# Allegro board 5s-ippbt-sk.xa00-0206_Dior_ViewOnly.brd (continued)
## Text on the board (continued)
User.45: list("[Package] BOTTOM" "196.Pkg to Place Keepin Spacing" "0 MIL [NONE]" "0 MIL" "0.00 MIL" "DRC ERROR CLASS/PACKAGE_BOTTOM" "[Shape] Package Keepin/All ((-353.71 -312.37) (4448.18 4461.96))" "[Shape] Package Geometry/Place_Bound_Bottom ((-360.18 172.48) (-131.49 627.92))" list(-353.710000 172.480000) nil)@@@list("amy_chou" "2015/01/12 09:59:30" nil "P143000034-PC" "5s-ippbt-sk.x01")@@@list("jennifer_hsu" "2015/01/12 14:37:48" nil "p143000039-pc" "5s-ippbt-sk.x01") | list("[Package] TOP" "146.Pkg to Place Keepin Spacing" "0 MIL [NONE]" "0 MIL" "0.00 MIL" "DRC ERROR CLASS/PACKAGE_TOP" "[Shape] Package Keepin/All ((-353.71 -312.37) (4448.18 4461.96))" "[Shape] Package Geometry/Place_Bound_Top ((-416.13 1530.26) (300.78 2667.86))" list(-314.340000 2622.640000) nil)@@@list("amy_chou" "2015/01/12 09:58:59" nil "P143000034-PC" "5s-ippbt-sk.x01")@@@list("jennifer_hsu" "2015/01/12 14:37:29" nil "p143000039-pc" "5s-ippbt-sk.x01") | list("[Package] TOP" "1.Pkg to Place Keepout Spacing" "0 MIL [NONE]" "122.05 MIL" "-122.05 MIL" "DRC ERROR CLASS/PACKAGE_TOP" "[Shape] Package Geometry/Place_Bound_Top ((-416.13 1530.26) (300.78 2667.86))" "[Shape] Package Keepout/Top ((-436.13 1510.26) (320.78 2687.86))" list(-287.050000 2630.860000) nil)@@@list("amy_chou" "2015/01/12 12:03:11" nil "P143000034-PC" "5s-ippbt-sk.x01")@@@nil | list("[Package] TOP" "145.Pkg to Place Keepout Spacing" "0 MIL [NONE]" "122.05 MIL" "-122.05 MIL" "DRC ERROR CLASS/PACKAGE_TOP" "[Shape] Package Keepout/Top ((-436.13 1510.26) (320.78 2687.86))" "[Shape] Package Geometry/Place_Bound_Top ((-416.13 1530.26) (300.78 2667.86))" list(-287.050000 1547.100000) nil)@@@list("amy_chou" "2015/01/12 09:58:59" nil "P143000034-PC" "5s-ippbt-sk.x01")@@@list("jennifer_hsu" "2015/01/12 14:37:28" nil "p143000039-pc" "5s-ippbt-sk.x01") | list("[Package] BOTTOM" "195.Pkg to Place Keepout Spacing" "0 MIL [NONE]" "198.82 MIL" "-198.82 MIL" "DRC ERROR CLASS/PACKAGE_BOTTOM" "[Shape] Package Keepout/Bottom ((-380.18 152.48) (-111.49 647.92))" "[Shape] Package Geometry/Place_Bound_Bottom ((-360.18 172.48) (-131.49 627.92))" list(-174.800000 627.920000) nil)@@@list("amy_chou" "2015/01/12 09:59:28" nil "P143000034-PC" "5s-ippbt-sk.x01")@@@list("jennifer_hsu" "2015/01/12 14:37:46" nil "p143000039-pc" "5s-ippbt-sk.x01") | list("[Package] BOTTOM" "4.Pkg to Place Keepout Spacing" "0 MIL [NONE]" "198.82 MIL" "-198.82 MIL" "DRC ERROR CLASS/PACKAGE_BOTTOM" "[Shape] Package Geometry/Place_Bound_Bottom ((-360.18 172.48) (-131.49 627.92))" "[Shape] Package Keepout/Bottom ((-380.18 152.48) (-111.49 647.92))" list(-174.800000 172.480000) nil)@@@list("amy_chou" "2015/01/09 17:09:16" nil "P143000034-PC" "5s-ippbt-sk.x01")@@@nil | list("[Package] BOTTOM" "181.Pkg to Place Keepout Spacing" "0 MIL [NONE]" "120 MIL" "-120.00 MIL" "DRC ERROR CLASS/PACKAGE_BOTTOM" "[Shape] Package Keepout/Bottom ((-380.18 152.48) (-111.49 647.92))" "[Shape] Package Geometry/Place_Bound_Bottom ((-237.19 -217.5) (197.81 217.5))" list(-154.910000 170.360000) nil)@@@list("amy_chou" "2015/01/12 09:59:19" nil "P143000034-PC" "5s-ippbt-sk.x01")@@@list("jennifer_hsu" "2015/01/12 14:37:41" nil "p143000039-pc" "5s-ippbt-sk.x01") | list("[Electrical] ALL" "127.Diffpair Max Uncoupled Length" "200 MIL [DIFFP_UNCOUPLED_LENGTH]" "226.3 MIL" "-26.30 MIL" "DRC ERROR CLASS/ALL" "[PinPair] <uTiL>cId2142<uTiL>.6:<uTiL>cId3537<uTiL>.AP10 ((-107.83 1959.21) (2741.31 1776.12))" "[PinPair] <uTiL>cId2142<uTiL>.5:<uTiL>cId3537<uTiL>.AP12 ((-107.83 1939.53) (2713.31 1776.12))" list(-107.830000 1939.530000) nil)@@@list("amy_chou" "2015/01/12 09:58:39" nil "P143000034-PC" "5s-ippbt-sk.x01")@@@list("jennifer_hsu" "2015/01/12 14:37:22" nil "p143000039-pc" "5s-ippbt-sk.x01") | list("[Package] TOP" "176.Pkg to Place Keepout Spacing" "0 MIL [NONE]" "78.74 MIL" "-78.74 MIL" "DRC ERROR CLASS/PACKAGE_TOP" "[Shape] Package Geometry/Place_Bound_Top ((-352.8 339.49) (-29.57 800.51))" "[Shape] Package Keepout/Top ((-372.8 319.49) (-9.57 820.51))" list(-29.570000 676.590000) nil)@@@list("amy_chou" "2015/01/12 09:59:16" nil "P143000034-PC" "5s-ippbt-sk.x01")@@@list("jennifer_hsu" "2015/01/12 14:37:39" nil "p143000039-pc" "5s-ippbt-sk.x01") | list("[Package] TOP" "171.Pkg to Pkg Spacing" "0 MIL [PACKAGE_HEIGHT_MIN]" "2 MIL" "-2.00 MIL" "DRC ERROR CLASS/PACKAGE_TOP" "[Shape] Package Geometry/Place_Bound_Top ((274.99 2677.45) (636.01 2871.55))" "[Shape] Package Geometry/Place_Bound_Top ((519.0 2748.19) (561.0 2791.81))" list(519.000000 2748.190000) nil)@@@list("amy_chou" "2015/01/12 09:59:14" nil "P143000034-PC" "5s-ippbt-sk.x01")@@@list("jennifer_hsu" "2015/01/12 14:37:38" nil "p143000039-pc" "5s-ippbt-sk.x01") | list("[Package] TOP" "162.Pkg to Place Keepout Spacing" "0 MIL [NONE]" "385.83 MIL" "-385.83 MIL" "DRC ERROR CLASS/PACKAGE_TOP" "[Shape] Package Geometry/Place_Bound_Top ((299.6 4003.36) (734.89 4575.0))" "[Shape] Package Keepout/Top ((219.6 3923.36) (814.89 4655.0))" list(535.930000 4007.140000) nil)@@@list("amy_chou" "2015/01/12 09:59:09" nil "P143000034-PC" "5s-ippbt-sk.x01")@@@list("jennifer_hsu" "2015/01/12 14:37:34" nil "p143000039-pc" "5s-ippbt-sk.x01") | list("[Package] TOP" "163.Pkg to Place Keepout Spacing" "0 MIL [PACKAGE_HEIGHT_MIN]" "385.83 MIL" "-385.83 MIL" "DRC ERROR CLASS/PACKAGE_TOP" "[Shape] Package Keepout/Top ((669.05 3600.32) (1555.75 4628.27))" "[Shape] Package Geometry/Place_Bound_Top ((299.6 4003.36) (734.89 4575.0))" list(669.050000 4015.550000) nil)@@@list("amy_chou" "2015/01/12 09:59:10" nil "P143000034-PC" "5s-ippbt-sk.x01")@@@list("jennifer_hsu" "2015/01/12 14:37:35" nil "p143000039-pc" "5s-ippbt-sk.x01") | list("[Package] TOP" "164.Pkg to Place Keepin Spacing" "0 MIL [NONE]" "0 MIL" "0.00 MIL" "DRC ERROR CLASS/PACKAGE_TOP" "[Shape] Package Keepin/All ((-353.71 -312.37) (4448.18 4461.96))" "[Shape] Package Geometry/Place_Bound_Top ((299.6 4003.36) (734.89 4575.0))" list(722.620000 4430.470000) nil)@@@list("amy_chou" "2015/01/12 09:59:10" nil "P143000034-PC" "5s-ippbt-sk.x01")@@@list("jennifer_hsu" "2015/01/12 14:37:35" nil "p143000039-pc" "5s-ippbt-sk.x01") | list("[Package] BOTTOM" "184.Pkg to Place Keepout Spacing" "0 MIL [NONE]" "393.7 MIL" "-393.70 MIL" "DRC ERROR CLASS/PACKAGE_BOTTOM" "[Shape] Package Keepout/Bottom ((728.52 749.93) (1290.38 3419.93))" "[Shape] Package Geometry/Place_Bound_Bottom ((145.87 510.78) (1222.38 3660.74))" list(728.520000 3335.560000) nil)@@@list("amy_chou" "2015/01/12 09:59:20" nil "P143000034-PC" "5s-ippbt-sk.x01")@@@list("jennifer_hsu" "2015/01/12 14:37:42" nil "p143000039-pc" "5s-ippbt-sk.x01") | list("[Package] TOP" "140.Pkg to Place Keepin Spacing" "0 MIL [NONE]" "0 MIL" "0.00 MIL" "DRC ERROR CLASS/PACKAGE_TOP" "[Shape] Package Keepin/All ((-353.71 -312.37) (4448.18 4461.96))" "[Shape] Package Geometry/Place_Bound_Top ((747.79 3679.06) (1477.01 4549.53))" list(790.350000 4430.470000) nil)@@@list("amy_chou" "2015/01/12 09:58:56" nil "P143000034-PC" "5s-ippbt-sk.x01")@@@list("jennifer_hsu" "2015/01/12 14:37:27" nil "p143000039-pc" "5s-ippbt-sk.x01") | list("[Package] TOP" "139.Pkg to Place Keepout Spacing" "0 MIL [NONE]" "656.69 MIL" "-656.69 MIL" "DRC ERROR CLASS/PACKAGE_TOP" "[Shape] Package Keepout/Top ((219.6 3923.36) (814.89 4655.0))" "[Shape] Package Geometry/Place_Bound_Top ((747.79 3679.06) (1477.01 4549.53))" list(802.620000 4549.530000) nil)@@@list("amy_chou" "2015/01/12 09:58:56" nil "P143000034-PC" "5s-ippbt-sk.x01")@@@list("jennifer_hsu" "2015/01/12 14:37:26" nil "p143000039-pc" "5s-ippbt-sk.x01") | list("[Package] TOP" "170.Pkg to Pkg Spacing" "0 MIL [PACKAGE_HEIGHT_MIN]" "248.03 MIL" "-248.03 MIL" "DRC ERROR CLASS/PACKAGE_TOP" "[Shape] Package Geometry/Place_Bound_Top ((800.94 1123.19) (856.56 1216.81))" "[Shape] Package Geometry/Place_Bound_Top ((686.82 1164.47) (970.68 1535.53))" list(856.560000 1164.470000) nil)@@@list("amy_chou" "2015/01/12 09:59:13" nil "P143000034-PC" "5s-ippbt-sk.x01")@@@list("jennifer_hsu" "2015/01/12 14:37:37" nil "p143000039-pc" "5s-ippbt-sk.x01") | list("[Package] BOTTOM" "190.Pkg to Pkg Spacing" "0 MIL [PACKAGE_HEIGHT_MIN]" "2 MIL" "-2.00 MIL" "DRC ERROR CLASS/PACKAGE_BOTTOM" "[Shape] Package Geometry/Place_Bound_Bottom ((913.39 482.9) (956.61 565.1))" "[Shape] Package Geometry/Place_Bound_Bottom ((863.19 462.19) (956.81 517.81))" list(913.390000 517.810000) nil)@@@list("amy_chou" "2015/01/12 09:59:24" nil "P143000034-PC" "5s-ippbt-sk.x01")@@@list("jennifer_hsu" "2015/01/12 14:37:44" nil "p143000039-pc" "5s-ippbt-sk.x01") | list("[Package] BOTTOM" "185.Pkg to Pkg Spacing" "0 MIL [PACKAGE_HEIGHT_MIN]" "248.03 MIL" "-248.03 MIL" "DRC ERROR CLASS/PACKAGE_BOTTOM" "[Shape] Package Geometry/Place_Bound_Bottom ((877.19 92.19) (970.81 147.81))" "[Shape] Package Geometry/Place_Bound_Bottom ((714.47 58.07) (1085.53 341.93))" list(924.000000 92.190000) nil)@@@list("amy_chou" "2015/01/12 09:59:21" nil "P143000034-PC" "5s-ippbt-sk.x01")@@@list("jennifer_hsu" "2015/01/12 14:37:42" nil "p143000039-pc" "5s-ippbt-sk.x01") | list("[Electrical] ALL" "135.Diffpair Max Uncoupled Length" "200 MIL [DIFFP_UNCOUPLED_LENGTH]" "258.41 MIL" "-58.41 MIL" "DRC ERROR CLASS/ALL" "[PinPair] <uTiL>cId3537<uTiL>.M52:<uTiL>cId1656<uTiL>.135 ((1924.04 2196.55) (1170.87 1654.66))" "[PinPair] <uTiL>cId3537<uTiL>.N53:<uTiL>cId1656<uTiL>.137 ((1908.88 2177.42) (1170.87 1631.04))" list(1170.870000 1631.040000) nil)@@@list("amy_chou" "2015/01/12 09:58:53" nil "P143000034-PC" "5s-ippbt-sk.x01")@@@list("jennifer_hsu" "2015/01/12 14:37:25" nil "p143000039-pc" "5s-ippbt-sk.x01") | list("[Package] BOTTOM" "189.Pkg to Pkg Spacing" "0 MIL [PACKAGE_HEIGHT_MIN]" "21.65 MIL" "-21.65 MIL" "DRC ERROR CLASS/PACKAGE_BOTTOM" "[Shape] Package Geometry/Place_Bound_Bottom ((1254.37 3476.81) (1325.63 3603.19))" "[Shape] Package Geometry/Place_Bound_Bottom ((1246.69 3478.98) (1333.31 3601.02))" list(1254.370000 3478.980000) nil)@@@list("amy_chou" "2015/01/12 09:59:23" nil "P143000034-PC" "5s-ippbt-sk.x01")@@@list("jennifer_hsu" "2015/01/12 14:37:44" nil "p143000039-pc" "5s-ippbt-sk.x01") | list("[Package] BOTTOM" "179.Pkg to Place Keepout Spacing" "0 MIL [NONE]" "70.87 MIL" "-70.87 MIL" "DRC ERROR CLASS/PACKAGE_BOTTOM" "[Shape] Package Keepout/Bottom ((728.52 749.93) (1290.38 3419.93))" "[Shape] Package Geometry/Place_Bound_Bottom ((1289.1 2201.54) (1569.12 2481.56))" list(1290.380000 2360.440000) nil)@@@list("amy_chou" "2015/01/12 09:59:18" nil "P143000034-PC" "5s-ippbt-sk.x01")@@@list("jennifer_hsu" "2015/01/12 14:37:40" nil "p143000039-pc" "5s-ippbt-sk.x01") | list("[Package] BOTTOM" "180.Pkg to Place Keepout Spacing" "0 MIL [NONE]" "70.87 MIL" "-70.87 MIL" "DRC ERROR CLASS/PACKAGE_BOTTOM" "[Shape] Package Keepout/Bottom ((728.52 749.93) (1290.38 3419.93))" "[Shape] Package Geometry/Place_Bound_Bottom ((1289.1 1414.14) (1569.12 1694.16))" list(1290.380000 1573.040000) nil)@@@list("amy_chou" "2015/01/12 09:59:18" nil "P143000034-PC" "5s-ippbt-sk.x01")@@@list("jennifer_hsu" "2015/01/12 14:37:41" nil "p143000039-pc" "5s-ippbt-sk.x01") | list("[Package] BOTTOM" "178.Pkg to Place Keepout Spacing" "0 MIL [NONE]" "220.47 MIL" "-220.47 MIL" "DRC ERROR CLASS/PACKAGE_BOTTOM" "[Shape] Package Keepout/Bottom ((728.52 749.93) (1290.38 3419.93))" "[Shape] Package Geometry/Place_Bound_Bottom ((1279.1 1044.99) (1579.12 1345.01))" list(1290.380000 1252.070000) nil)@@@list("amy_chou" "2015/01/12 09:59:17" nil "P143000034-PC" "5s-ippbt-sk.x01")@@@list("jennifer_hsu" "2015/01/12 14:37:40" nil "p143000039-pc" "5s-ippbt-sk.x01") | list("[Package] BOTTOM" "188.Pkg to Pkg Spacing" "0 MIL [PACKAGE_HEIGHT_MIN]" "21.65 MIL" "-21.65 MIL" "DRC ERROR CLASS/PACKAGE_BOTTOM" "[Shape] Package Geometry/Place_Bound_Bottom ((1344.37 3476.81) (1415.63 3603.19))" "[Shape] Package Geometry/Place_Bound_Bottom ((1336.69 3478.98) (1423.31 3601.02))" list(1344.370000 3478.980000) nil)@@@list("amy_chou" "2015/01/12 09:59:22" nil "P143000034-PC" "5s-ippbt-sk.x01")@@@list("jennifer_hsu" "2015/01/12 14:37:44" nil "p143000039-pc" "5s-ippbt-sk.x01") | list("[Package] TOP" "7.Pkg to Place Keepout Spacing" "0 MIL [PACKAGE_HEIGHT_MIN]" "656.69 MIL" "-656.69 MIL" "DRC ERROR CLASS/PACKAGE_TOP" "[Shape] Package Keepout/Top ((1418.61 3744.77) (2204.99 4634.92))" "[Shape] Package Geometry/Place_Bound_Top ((747.79 3679.06) (1477.01 4549.53))" list(1418.610000 4549.530000) nil)@@@list("amy_chou" "2015/01/12 18:28:01" nil "P143000034-PC" "5s-ippbt-sk.x01")@@@list("jennifer_hsu" "2015/01/12 18:35:55" nil "p143000039-pc" "5s-ippbt-sk.x01") | list("[Package] TOP" "137.Pkg to Place Keepout Spacing" "0 MIL [PACKAGE_HEIGHT_MIN]" "656.69 MIL" "-656.69 MIL" "DRC ERROR CLASS/PACKAGE_TOP" "[Shape] Package Keepout/Top ((669.05 3600.32) (1555.75 4628.27))" "[Shape] Package Geometry/Place_Bound_Top ((747.79 3679.06) (1477.01 4549.53))" list(1434.450000 4127.920000) nil)@@@list("amy_chou" "2015/01/12 09:58:55" nil "P143000034-PC" "5s-ippbt-sk.x01")@@@list("jennifer_hsu" "2015/01/12 14:37:26" nil "p143000039-pc" "5s-ippbt-sk.x01") | list("[Package] TOP" "138.Pkg to Place Keepout Spacing" "0 MIL [NONE]" "656.69 MIL" "-656.69 MIL" "DRC ERROR CLASS/PACKAGE_TOP" "[Shape] Package Keepout/Top ((1418.61 3750.77) (2204.99 4634.92))" "[Shape] Package Geometry/Place_Bound_Top ((747.79 3679.06) (1477.01 4549.53))" list(1434.450000 3782.980000) nil)@@@list("amy_chou" "2015/01/12 09:58:55" nil "P143000034-PC" "5s-ippbt-sk.x01")@@@list("jennifer_hsu" "2015/01/12 14:37:26" nil "p143000039-pc" "5s-ippbt-sk.x01") | list("[Package] BOTTOM" "186.Pkg to Pkg Spacing" "0 MIL [PACKAGE_HEIGHT_MIN]" "21.65 MIL" "-21.65 MIL" "DRC ERROR CLASS/PACKAGE_BOTTOM" "[Shape] Package Geometry/Place_Bound_Bottom ((1449.81 3667.37) (1576.19 3738.63))" "[Shape] Package Geometry/Place_Bound_Bottom ((1451.98 3659.69) (1574.02 3746.31))" list(1451.980000 3667.370000) nil)@@@list("amy_chou" "2015/01/12 09:59:21" nil "P143000034-PC" "5s-ippbt-sk.x01")@@@list("jennifer_hsu" "2015/01/12 14:37:43" nil "p143000039-pc" "5s-ippbt-sk.x01") | list("[Package] BOTTOM" "187.Pkg to Pkg Spacing" "0 MIL [PACKAGE_HEIGHT_MIN]" "21.65 MIL" "-21.65 MIL" "DRC ERROR CLASS/PACKAGE_BOTTOM" "[Shape] Package Geometry/Place_Bound_Bottom ((1451.81 3569.37) (1578.19 3640.63))" "[Shape] Package Geometry/Place_Bound_Bottom ((1453.98 3561.69) (1576.02 3648.31))" list(1453.980000 3569.370000) nil)@@@list("amy_chou" "2015/01/12 09:59:22" nil "P143000034-PC" "5s-ippbt-sk.x01")@@@list("jennifer_hsu" "2015/01/12 14:37:43" nil "p143000039-pc" "5s-ippbt-sk.x01") | list("[Package] TOP" "152.Pkg to Place Keepin Spacing" "0 MIL [NONE]" "0 MIL" "0.00 MIL" "DRC ERROR CLASS/PACKAGE_TOP" "[Shape] Package Keepin/All ((-353.71 -312.37) (4448.18 4461.96))" "[Shape] Package Geometry/Place_Bound_Top ((1498.61 3830.77) (2124.99 4554.92))" list(1498.610000 4430.470000) nil)@@@list("amy_chou" "2015/01/12 09:59:03" nil "P143000034-PC" "5s-ippbt-sk.x01")@@@list("jennifer_hsu" "2015/01/12 14:37:31" nil "p143000039-pc" "5s-ippbt-sk.x01") | list("[Package] TOP" "5.Pkg to Place Keepin Spacing" "0 MIL [NONE]" "0 MIL" "0.00 MIL" "DRC ERROR CLASS/PACKAGE_TOP" "[Shape] Package Keepin/All ((-353.71 -312.37) (4448.18 4461.96))" "[Shape] Package Geometry/Place_Bound_Top ((1498.61 3824.77) (2124.99 4554.92))" list(1498.610000 4430.470000) nil)@@@list("amy_chou" "2015/01/12 17:57:22" nil "P143000034-PC" "5s-ippbt-sk.x01")@@@list("jennifer_hsu" "2015/01/12 18:35:54" nil "p143000039-pc" "5s-ippbt-sk.x01") | list("[Package] TOP" "3.Pkg to Place Keepout Spacing" "0 MIL [PACKAGE_HEIGHT_MIN]" "639.76 MIL" "-639.76 MIL" "DRC ERROR CLASS/PACKAGE_TOP" "[Shape] Package Keepout/Top ((1418.61 3744.77) (2204.99 4634.92))" "[Shape] Package Geometry/Place_Bound_Top ((1498.61 3824.77) (2124.99 4554.92))" list(1498.610000 3824.770000) nil)@@@list("amy_chou" "2015/01/12 18:28:06" nil "P143000034-PC" "5s-ippbt-sk.x01")@@@list("jennifer_hsu" "2015/01/12 18:35:53" nil "p143000039-pc" "5s-ippbt-sk.x01") | list("[Package] TOP" "150.Pkg to Place Keepout Spacing" "0 MIL [PACKAGE_HEIGHT_MIN]" "639.76 MIL" "-639.76 MIL" "DRC ERROR CLASS/PACKAGE_TOP" "[Shape] Package Keepout/Top ((669.05 3600.32) (1555.75 4628.27))" "[Shape] Package Geometry/Place_Bound_Top ((1498.61 3830.77) (2124.99 4554.92))" list(1513.190000 4127.920000) nil)@@@list("amy_chou" "2015/01/12 09:59:02" nil "P143000034-PC" "5s-ippbt-sk.x01")@@@list("jennifer_hsu" "2015/01/12 14:37:30" nil "p143000039-pc" "5s-ippbt-sk.x01") | list("[Package] TOP" "4.Pkg to Place Keepout Spacing" "0 MIL [PACKAGE_HEIGHT_MIN]" "639.76 MIL" "-639.76 MIL" "DRC ERROR CLASS/PACKAGE_TOP" "[Shape] Package Keepout/Top ((669.05 3600.32) (1555.75 4628.27))" "[Shape] Package Geometry/Place_Bound_Top ((1498.61 3824.77) (2124.99 4554.92))" list(1513.190000 4127.920000) nil)@@@list("amy_chou" "2015/01/12 18:27:59" nil "P143000034-PC" "5s-ippbt-sk.x01")@@@list("jennifer_hsu" "2015/01/12 18:35:53" nil "p143000039-pc" "5s-ippbt-sk.x01") | list("[Package] TOP" "3.Pkg to Place Keepout Spacing" "0 MIL [PACKAGE_HEIGHT_MIN]" "639.76 MIL" "-639.76 MIL" "DRC ERROR CLASS/PACKAGE_TOP" "[Shape] Package Keepout/Top ((669.05 3600.32) (1555.75 4628.27))" "[Shape] Package Geometry/Place_Bound_Top ((1498.61 3824.77) (2124.99 4554.92))" list(1513.190000 3824.770000) nil)@@@list("amy_chou" "2015/01/12 17:57:28" nil "P143000034-PC" "5s-ippbt-sk.x01")@@@nil | list("[Package] TOP" "158.Pkg to Place Keepout Spacing" "0 MIL [NONE]" "165.35 MIL" "-165.35 MIL" "DRC ERROR CLASS/PACKAGE_TOP" "[Shape] Package Geometry/Place_Bound_Top ((1348.69 -332.07) (1730.95 554.15))" "[Shape] Package Keepout/Top ((1328.69 -352.07) (1750.95 574.15))" list(1730.950000 111.040000) nil)@@@list("amy_chou" "2015/01/12 09:59:07" nil "P143000034-PC" "5s-ippbt-sk.x01")@@@list("jennifer_hsu" "2015/01/12 14:37:33" nil "p143000039-pc" "5s-ippbt-sk.x01") | list("[Package] TOP" "159.Pkg to Place Keepin Spacing" "0 MIL [NONE]" "0 MIL" "0.00 MIL" "DRC ERROR CLASS/PACKAGE_TOP" "[Shape] Package Keepin/All ((-353.71 -312.37) (4448.18 4461.96))" "[Shape] Package Geometry/Place_Bound_Top ((1348.69 -332.07) (1730.95 554.15))" list(1730.950000 -266.490000) nil)@@@list("amy_chou" "2015/01/12 09:59:07" nil "P143000034-PC" "5s-ippbt-sk.x01")@@@list("jennifer_hsu" "2015/01/12 14:37:33" nil "p143000039-pc" "5s-ippbt-sk.x01") | list("[Package] TOP" "151.Pkg to Place Keepout Spacing" "0 MIL [NONE]" "639.76 MIL" "-639.76 MIL" "DRC ERROR CLASS/PACKAGE_TOP" "[Shape] Package Keepout/Top ((1418.61 3750.77) (2204.99 4634.92))" "[Shape] Package Geometry/Place_Bound_Top ((1498.61 3830.77) (2124.99 4554.92))" list(1811.800000 3830.770000) nil)@@@list("amy_chou" "2015/01/12 09:59:03" nil "P143000034-PC" "5s-ippbt-sk.x01")@@@list("jennifer_hsu" "2015/01/12 14:37:31" nil "p143000039-pc" "5s-ippbt-sk.x01") | list("[Package] TOP" "172.Pkg to Pkg Spacing" "0 MIL [PACKAGE_HEIGHT_MIN]" "47.24 MIL" "-47.24 MIL" "DRC ERROR CLASS/PACKAGE_TOP" "[Shape] Package Geometry/Place_Bound_Top ((1822.19 933.19) (1877.81 1026.81))" "[Shape] Package Geometry/Place_Bound_Top ((1600.35 958.49) (1904.12 1201.5))" list(1822.190000 1026.810000) nil)@@@list("amy_chou" "2015/01/12 09:59:14" nil "P143000034-PC" "5s-ippbt-sk.x01")@@@list("jennifer_hsu" "2015/01/12 14:37:38" nil "p143000039-pc" "5s-ippbt-sk.x01") | list("[Package] BOTTOM" "183.Pkg to Place Keepout Spacing" "0 MIL [NONE]" "43.31 MIL" "-43.31 MIL" "DRC ERROR CLASS/PACKAGE_BOTTOM" "[Shape] Package Geometry/Place_Bound_Bottom ((1828.98 -6.97) (1998.66 646.97))" "[Shape] Package Keepout/Bottom ((1808.98 -26.97) (2018.66 666.97))" list(1828.980000 320.000000) nil)@@@list("amy_chou" "2015/01/12 09:59:20" nil "P143000034-PC" "5s-ippbt-sk.x01")@@@list("jennifer_hsu" "2015/01/12 14:37:42" nil "p143000039-pc" "5s-ippbt-sk.x01") | list("[Electrical] ALL" "133.Relative Propagation Delay" "R_M_A_D7:G:::0.00 MIL:19.00 MIL [RELATIVE_PROPAGATION_DELAY]" "30.58 MIL" "" "DRC ERROR CLASS/ALL" "[PinPair] <uTiL>cId3537<uTiL>.AA51:<uTiL>cId1656<uTiL>.186 ((1938.15 2024.38) (848.03 1052.3))" "[PinPair] <uTiL>cId3537<uTiL>.AC53:<uTiL>cId1656<uTiL>.192 ((1908.88 1986.12) (848.03 981.43))" list(1908.880000 1986.120000) nil)@@@list("amy_chou" "2015/01/12 09:58:45" nil "P143000034-PC" "5s-ippbt-sk.x01")@@@list("jennifer_hsu" "2015/01/12 14:37:24" nil "p143000039-pc" "5s-ippbt-sk.x01") | list("[Electrical] ALL" "136.Diffpair Max Uncoupled Length" "200 MIL [DIFFP_UNCOUPLED_LENGTH]" "260.19 MIL" "-60.19 MIL" "DRC ERROR CLASS/ALL" "[PinPair] <uTiL>cId3537<uTiL>.N53:<uTiL>cId1656<uTiL>.137 ((1908.88 2177.42) (1170.87 1631.04))" "[PinPair] <uTiL>cId3537<uTiL>.M52:<uTiL>cId1656<uTiL>.135 ((1924.04 2196.55) (1170.87 1654.66))" list(1924.040000 2196.550000) nil)@@@list("amy_chou" "2015/01/12 09:58:54" nil "P143000034-PC" "5s-ippbt-sk.x01")@@@list("jennifer_hsu" "2015/01/12 14:37:25" nil "p143000039-pc" "5s-ippbt-sk.x01") | list("[Electrical] ALL" "134.Relative Propagation Delay" "R_M_A_D1:G:::0.00 MIL:19.00 MIL [RELATIVE_PROPAGATION_DELAY]" "39.19 MIL" "" "DRC ERROR CLASS/ALL" "[PinPair] <uTiL>cId3537<uTiL>.B34:<uTiL>cId1656<uTiL>.27 ((2279.46 2397.82) (1170.87 3024.74))" "[PinPair] <uTiL>cId3537<uTiL>.A37:<uTiL>cId1656<uTiL>.34 ((2222.07 2412.98) (848.03 2942.06))" list(2222.070000 2412.980000) nil)@@@list("amy_chou" "2015/01/12 09:58:52" nil "P143000034-PC" "5s-ippbt-sk.x01")@@@list("jennifer_hsu" "2015/01/12 14:37:25" nil "p143000039-pc" "5s-ippbt-sk.x01") | list("[Package] TOP" "155.Pkg to Place Keepin Spacing" "0 MIL [NONE]" "0 MIL" "0.00 MIL" "DRC ERROR CLASS/PACKAGE_TOP" "[Shape] Package Keepin/All ((-353.71 -312.37) (4448.18 4461.96))" "[Shape] Package Geometry/Place_Bound_Top ((2323.9 3629.31) (2669.82 4573.62))" list(2323.900000 4376.560000) nil)@@@list("amy_chou" "2015/01/12 09:59:05" nil "P143000034-PC" "5s-ippbt-sk.x01")@@@list("jennifer_hsu" "2015/01/12 14:37:32" nil "p143000039-pc" "5s-ippbt-sk.x01") | list("[Package] BOTTOM" "177.Pkg to Pkg Spacing" "0 MIL [PACKAGE_HEIGHT_MIN]" "57.09 MIL" "-57.09 MIL" "DRC ERROR CLASS/PACKAGE_BOTTOM" "[Shape] Package Geometry/Place_Bound_Bottom ((2347.19 758.19) (2402.81 851.81))" "[Shape] Package Geometry/Place_Bound_Bottom ((2284.91 733.54) (2395.09 796.46))" list(2347.190000 758.190000) nil)@@@list("amy_chou" "2015/01/12 09:59:17" nil "P143000034-PC" "5s-ippbt-sk.x01")@@@list("jennifer_hsu" "2015/01/12 14:37:40" nil "p143000039-pc" "5s-ippbt-sk.x01") | list("[Package] TOP" "153.Pkg to Place Keepout Spacing" "0 MIL [NONE]" "354.33 MIL" "-354.33 MIL" "DRC ERROR CLASS/PACKAGE_TOP" "[Shape] Package Keepout/Top ((2297.99 -322.01) (2642.01 -177.99))" "[Shape] Package Geometry/Place_Bound_Top ((2307.99 -312.01) (2632.01 -187.99))" list(2470.000000 -187.990000) nil)@@@list("amy_chou" "2015/01/12 09:59:04" nil "P143000034-PC" "5s-ippbt-sk.x01")@@@list("jennifer_hsu" "2015/01/12 14:37:31" nil "p143000039-pc" "5s-ippbt-sk.x01") | list("[Electrical] ALL" "114.Diffpair Max Uncoupled Length" "200 MIL [DIFFP_UNCOUPLED_LENGTH]" "221.63 MIL" "-21.63 MIL" "DRC ERROR CLASS/ALL" "[PinPair] <uTiL>cId4704<uTiL>.3:<uTiL>cId3537<uTiL>.AG1 ((2477.17 4106.69) (2917.86 1909.6))" "[PinPair] <uTiL>cId4704<uTiL>.1:<uTiL>cId3537<uTiL>.AG3 ((2477.17 4152.16) (2888.59 1909.6))" list(2477.170000 4152.160000) nil)@@@list("amy_chou" "2015/01/12 09:58:30" nil "P143000034-PC" "5s-ippbt-sk.x01")@@@list("jennifer_hsu" "2015/01/12 14:37:17" nil "p143000039-pc" "5s-ippbt-sk.x01") | list("[Electrical] ALL" "116.Diffpair Max Uncoupled Length" "200 MIL [DIFFP_UNCOUPLED_LENGTH]" "212.82 MIL" "-12.82 MIL" "DRC ERROR CLASS/ALL" "[PinPair] <uTiL>cId4704<uTiL>.9:<uTiL>cId3537<uTiL>.AD2 ((2477.17 3970.27) (2902.7 1966.99))" "[PinPair] <uTiL>cId4704<uTiL>.7:<uTiL>cId3537<uTiL>.AD3 ((2477.17 4015.75) (2874.6 1966.75))" list(2477.170000 4015.750000) nil)@@@list("amy_chou" "2015/01/12 09:58:31" nil "P143000034-PC" "5s-ippbt-sk.x01")@@@list("jennifer_hsu" "2015/01/12 14:37:18" nil "p143000039-pc" "5s-ippbt-sk.x01") | list("[Package] TOP" "173.Pkg to Pkg Spacing" "0 MIL [PACKAGE_HEIGHT_MIN]" "2 MIL" "-2.00 MIL" "DRC ERROR CLASS/PACKAGE_TOP" "[Shape] Package Geometry/Place_Bound_Top ((2488.19 2807.19) (2581.81 2862.81))" "[Shape] Package Geometry/Place_Bound_Top ((2488.19 2857.19) (2581.81 2912.81))" list(2488.190000 2862.810000) nil)@@@list("amy_chou" "2015/01/12 09:59:15" nil "P143000034-PC" "5s-ippbt-sk.x01")@@@list("jennifer_hsu" "2015/01/12 14:37:38" nil "p143000039-pc" "5s-ippbt-sk.x01") | list("[Electrical] ALL" "117.Diffpair Max Uncoupled Length" "200 MIL [DIFFP_UNCOUPLED_LENGTH]" "225.09 MIL" "-25.09 MIL" "DRC ERROR CLASS/ALL" "[PinPair] <uTiL>cId3537<uTiL>.AF2:<uTiL>cId4704<uTiL>.6 ((2902.7 1928.73) (2516.54 4038.46))" "[PinPair] <uTiL>cId4704<uTiL>.4:<uTiL>cId3537<uTiL>.AF3 ((2516.54 4083.94) (2874.6 1928.97))" list(2516.540000 4083.940000) nil)@@@list("amy_chou" "2015/01/12 09:58:32" nil "P143000034-PC" "5s-ippbt-sk.x01")@@@list("jennifer_hsu" "2015/01/12 14:37:18" nil "p143000039-pc" "5s-ippbt-sk.x01") | list("[Electrical] ALL" "130.Diffpair Max Uncoupled Length" "200 MIL [DIFFP_UNCOUPLED_LENGTH]" "223.62 MIL" "-23.62 MIL" "DRC ERROR CLASS/ALL" "[PinPair] <uTiL>cId3537<uTiL>.K16:<uTiL>cId3653<uTiL>.2 ((2623.43 2236.43) (4025.91 1634.72))" "[PinPair] <uTiL>cId3537<uTiL>.M16:<uTiL>cId3653<uTiL>.3 ((2623.43 2208.43) (4025.91 1713.46))" list(2623.430000 2208.430000) nil)@@@list("amy_chou" "2015/01/12 09:58:42" nil "P143000034-PC" "5s-ippbt-sk.x01")@@@list("jennifer_hsu" "2015/01/12 14:37:23" nil "p143000039-pc" "5s-ippbt-sk.x01") | list("[Electrical] ALL" "132.Diffpair Max Uncoupled Length" "200 MIL [DIFFP_UNCOUPLED_LENGTH]" "207.92 MIL" "-7.92 MIL" "DRC ERROR CLASS/ALL" "[PinPair] <uTiL>cId3537<uTiL>.G14:<uTiL>cId4801<uTiL>.2 ((2662.43 2292.43) (4054.67 2459.84))" "[PinPair] <uTiL>cId3537<uTiL>.J14:<uTiL>cId4801<uTiL>.3 ((2662.43 2264.43) (4054.67 2538.58))" list(2662.430000 2264.430000) nil)@@@list("amy_chou" "2015/01/12 09:58:44" nil "P143000034-PC" "5s-ippbt-sk.x01")@@@list("jennifer_hsu" "2015/01/12 14:37:24" nil "p143000039-pc" "5s-ippbt-sk.x01") | list("[Package] TOP" "154.Pkg to Place Keepout Spacing" "0 MIL [NONE]" "655.51 MIL" "-655.51 MIL" "DRC ERROR CLASS/PACKAGE_TOP" "[Shape] Package Geometry/Place_Bound_Top ((2323.9 3629.31) (2669.82 4573.62))" "[Shape] Package Keepout/Top ((2243.9 3549.31) (2749.82 4653.62))" list(2669.820000 4573.620000) nil)@@@list("amy_chou" "2015/01/12 09:59:04" nil "P143000034-PC" "5s-ippbt-sk.x01")@@@list("jennifer_hsu" "2015/01/12 14:37:32" nil "p143000039-pc" "5s-ippbt-sk.x01") | list("[Package] TOP" "165.Pkg to Place Keepout Spacing" "0 MIL [NONE]" "259.84 MIL" "-259.84 MIL" "DRC ERROR CLASS/PACKAGE_TOP" "[Shape] Package Geometry/Place_Bound_Top ((2769.44 -179.29) (2970.56 309.29))" "[Shape] Package Keepout/Top ((2749.44 -199.29) (2990.56 329.29))" list(2769.440000 309.290000) nil)@@@list("amy_chou" "2015/01/12 09:59:11" nil "P143000034-PC" "5s-ippbt-sk.x01")@@@list("jennifer_hsu" "2015/01/12 14:37:35" nil "p143000039-pc" "5s-ippbt-sk.x01") | list("[Electrical] ALL" "124.Diffpair Max Uncoupled Length" "200 MIL [DIFFP_UNCOUPLED_LENGTH]" "216.83 MIL" "-16.83 MIL" "DRC ERROR CLASS/ALL" "[PinPair] <uTiL>cId3537<uTiL>.BF6:<uTiL>cId555<uTiL>.2 ((2811.51 1544.77) (-63.23 638.9))" "[PinPair] <uTiL>cId555<uTiL>.3:<uTiL>cId3537<uTiL>.BG7 ((-63.23 619.21) (2789.48 1526.24))" list(2789.480000 1526.240000) nil)@@@list("amy_chou" "2015/01/12 09:58:36" nil "P143000034-PC" "5s-ippbt-sk.x01")@@@list("jennifer_hsu" "2015/01/12 14:37:21" nil "p143000039-pc" "5s-ippbt-sk.x01") | list("[Electrical] ALL" "128.Diffpair Max Uncoupled Length" "200 MIL [DIFFP_UNCOUPLED_LENGTH]" "203.01 MIL" "-3.01 MIL" "DRC ERROR CLASS/ALL" "[PinPair] <uTiL>cId3537<uTiL>.AP4:<uTiL>cId3651<uTiL>.14 ((2851.82 1775.09) (1713.62 3532.83))" "[PinPair] <uTiL>cId3537<uTiL>.AP6:<uTiL>cId3651<uTiL>.13 ((2825.31 1776.12) (1697.87 3532.83))" list(2825.310000 1776.120000) nil)@@@list("amy_chou" "2015/01/12 09:58:40" nil "P143000034-PC" "5s-ippbt-sk.x01")@@@list("jennifer_hsu" "2015/01/12 14:37:22" nil "p143000039-pc" "5s-ippbt-sk.x01") | list("[Electrical] ALL" "126.Diffpair Max Uncoupled Length" "200 MIL [DIFFP_UNCOUPLED_LENGTH]" "211.55 MIL" "-11.55 MIL" "DRC ERROR CLASS/ALL" "[PinPair] <uTiL>cId3537<uTiL>.AV4:<uTiL>cId1927<uTiL>.37 ((2851.82 1698.8) (1688.44 120.88))" "[PinPair] <uTiL>cId3537<uTiL>.AV6:<uTiL>cId1927<uTiL>.35 ((2825.31 1698.8) (1688.44 140.57))" list(2825.310000 1698.800000) nil)@@@list("amy_chou" "2015/01/12 09:58:38" nil "P143000034-PC" "5s-ippbt-sk.x01")@@@list("jennifer_hsu" "2015/01/12 14:37:21" nil "p143000039-pc" "5s-ippbt-sk.x01") | list("[Package] TOP" "157.Pkg to Place Keepin Spacing" "0 MIL [NONE]" "0 MIL" "0.00 MIL" "DRC ERROR CLASS/PACKAGE_TOP" "[Shape] Package Keepin/All ((-353.71 -312.37) (4448.18 4461.96))" "[Shape] Package Geometry/Place_Bound_Top ((2895.24 3525.39) (3222.4 4573.03))" list(2895.240000 4430.470000) nil)@@@list("amy_chou" "2015/01/12 09:59:06" nil "P143000034-PC" "5s-ippbt-sk.x01")@@@list("jennifer_hsu" "2015/01/12 14:37:33" nil "p143000039-pc" "5s-ippbt-sk.x01") | list("[Package] TOP" "6.Pkg to Place Keepout Spacing" "0 MIL [PACKAGE_HEIGHT_MIN]" "710.63 MIL" "-710.63 MIL" "DRC ERROR CLASS/PACKAGE_TOP" "[Shape] Package Keepout/Top ((2815.24 3445.39) (3302.4 4653.03))" "[Shape] Package Geometry/Place_Bound_Top ((2895.24 3525.39) (3222.4 4573.03))" list(2895.240000 3525.390000) nil)@@@list("amy_chou" "2015/01/12 18:28:00" nil "P143000034-PC" "5s-ippbt-sk.x01")@@@list("jennifer_hsu" "2015/01/12 18:35:54" nil "p143000039-pc" "5s-ippbt-sk.x01") | list("[Electrical] ALL" "115.Diffpair Max Uncoupled Length" "200 MIL [DIFFP_UNCOUPLED_LENGTH]" "253.06 MIL" "-53.06 MIL" "DRC ERROR CLASS/ALL" "[PinPair] <uTiL>cId4704<uTiL>.10:<uTiL>cId3537<uTiL>.AC3 ((2516.54 3947.52) (2888.59 1986.12))" "[PinPair] <uTiL>cId3537<uTiL>.AC1:<uTiL>cId4704<uTiL>.12 ((2917.86 1986.12) (2516.54 3902.05))" list(2917.860000 1986.120000) nil)@@@list("amy_chou" "2015/01/12 09:58:31" nil "P143000034-PC" "5s-ippbt-sk.x01")@@@list("jennifer_hsu" "2015/01/12 14:37:17" nil "p143000039-pc" "5s-ippbt-sk.x01") | list("[Electrical] ALL" "118.Diffpair Max Uncoupled Length" "200 MIL [DIFFP_UNCOUPLED_LENGTH]" "357.3 MIL" "-157.30 MIL" "DRC ERROR CLASS/ALL" "[PinPair] <uTiL>cId4621<uTiL>.1:<uTiL>cId3537<uTiL>.AL3 ((3042.4 3395.59) (2888.59 1833.08))" "[PinPair] <uTiL>cId3537<uTiL>.AL1:<uTiL>cId4621<uTiL>.4 ((2917.86 1833.08) (2967.6 3344.41))" list(2917.860000 1833.080000) nil)@@@list("amy_chou" "2015/01/12 09:58:33" nil "P143000034-PC" "5s-ippbt-sk.x01")@@@list("jennifer_hsu" "2015/01/12 14:37:18" nil "p143000039-pc" "5s-ippbt-sk.x01") | list("[Electrical] ALL" "121.Diffpair Max Uncoupled Length" "200 MIL [DIFFP_UNCOUPLED_LENGTH]" "302.68 MIL" "-102.68 MIL" "DRC ERROR CLASS/ALL" "[PinPair] <uTiL>cId3537<uTiL>.AR3:<uTiL>cId4703<uTiL>.7 ((2888.59 1756.56) (3029.29 3929.92))" "[PinPair] <uTiL>cId3537<uTiL>.AR1:<uTiL>cId4703<uTiL>.9 ((2917.86 1756.56) (3029.29 3878.74))" list(2917.860000 1756.560000) nil)@@@list("amy_chou" "2015/01/12 09:58:35" nil "P143000034-PC" "5s-ippbt-sk.x01")@@@list("jennifer_hsu" "2015/01/12 14:37:19" nil "p143000039-pc" "5s-ippbt-sk.x01") | list("[Package] TOP" "147.Pkg to Place Keepout Spacing" "0 MIL [NONE]" "259.84 MIL" "-259.84 MIL" "DRC ERROR CLASS/PACKAGE_TOP" "[Shape] Package Geometry/Place_Bound_Top ((2769.44 -179.29) (2970.56 309.29))" "[Shape] Package Keepout/Top ((2919.55 -318.35) (3300.93 119.6))" list(2970.560000 -90.030000) nil)@@@list("amy_chou" "2015/01/12 09:59:00" nil "P143000034-PC" "5s-ippbt-sk.x01")@@@list("jennifer_hsu" "2015/01/12 14:37:29" nil "p143000039-pc" "5s-ippbt-sk.x01") | list("[Package] TOP" "5.Pkg to Place Keepout Spacing" "0 MIL [NONE]" "257.09 MIL" "-257.09 MIL" "DRC ERROR CLASS/PACKAGE_TOP" "[Shape] Package Geometry/Place_Bound_Top ((2999.55 -238.35) (3220.93 39.6))" "[Shape] Package Keepout/Top ((2919.55 -318.35) (3300.93 119.6))" list(2999.550000 -155.630000) nil)@@@list("amy_chou" "2015/01/12 18:28:03" nil "P143000034-PC" "5s-ippbt-sk.x01")@@@nil | list("[Package] TOP" "149.Pkg to Place Keepin Spacing" "0 MIL [NONE]" "0 MIL" "0.00 MIL" "DRC ERROR CLASS/PACKAGE_TOP" "[Shape] Package Keepin/All ((-353.71 -312.37) (4448.18 4461.96))" "[Shape] Package Geometry/Place_Bound_Top ((2999.55 -238.35) (3220.93 39.6))" list(3009.650000 -194.260000) nil)@@@list("amy_chou" "2015/01/12 09:59:02" nil "P143000034-PC" "5s-ippbt-sk.x01")@@@list("jennifer_hsu" "2015/01/12 14:37:30" nil "p143000039-pc" "5s-ippbt-sk.x01") | list("[Electrical] ALL" "122.Diffpair Max Uncoupled Length" "200 MIL [DIFFP_UNCOUPLED_LENGTH]" "334.83 MIL" "-134.83 MIL" "DRC ERROR CLASS/ALL" "[PinPair] <uTiL>cId3537<uTiL>.AR1:<uTiL>cId4703<uTiL>.9 ((2917.86 1756.56) (3029.29 3878.74))" "[PinPair] <uTiL>cId3537<uTiL>.AR3:<uTiL>cId4703<uTiL>.7 ((2888.59 1756.56) (3029.29 3929.92))" list(3029.290000 3929.920000) nil)@@@list("amy_chou" "2015/01/12 09:58:35" nil "P143000034-PC" "5s-ippbt-sk.x01")@@@list("jennifer_hsu" "2015/01/12 14:37:20" nil "p143000039-pc" "5s-ippbt-sk.x01") | list("[Electrical] ALL" "119.Diffpair Max Uncoupled Length" "200 MIL [DIFFP_UNCOUPLED_LENGTH]" "320.43 MIL" "-120.43 MIL" "DRC ERROR CLASS/ALL" "[PinPair] <uTiL>cId3537<uTiL>.AL1:<uTiL>cId4621<uTiL>.4 ((2917.86 1833.08) (2967.6 3344.41))" "[PinPair] <uTiL>cId4621<uTiL>.1:<uTiL>cId3537<uTiL>.AL3 ((3042.4 3395.59) (2888.59 1833.08))" list(3042.400000 3395.590000) nil)@@@list("amy_chou" "2015/01/12 09:58:33" nil "P143000034-PC" "5s-ippbt-sk.x01")@@@list("jennifer_hsu" "2015/01/12 14:37:19" nil "p143000039-pc" "5s-ippbt-sk.x01") | list("[Package] TOP" "156.Pkg to Place Keepout Spacing" "0 MIL [NONE]" "710.63 MIL" "-710.63 MIL" "DRC ERROR CLASS/PACKAGE_TOP" "[Shape] Package Keepout/Top ((2815.24 3445.39) (3302.4 4653.03))" "[Shape] Package Geometry/Place_Bound_Top ((2895.24 3525.39) (3222.4 4573.03))" list(3058.820000 3525.390000) nil)@@@list("amy_chou" "2015/01/12 09:59:05" nil "P143000034-PC" "5s-ippbt-sk.x01")@@@list("jennifer_hsu" "2015/01/12 14:37:32" nil "p143000039-pc" "5s-ippbt-sk.x01") | list("[Electrical] ALL" "120.Diffpair Max Uncoupled Length" "200 MIL [DIFFP_UNCOUPLED_LENGTH]" "220.7 MIL" "-20.70 MIL" "DRC ERROR CLASS/ALL" "[PinPair] <uTiL>cId3537<uTiL>.AT2:<uTiL>cId4703<uTiL>.4 ((2902.7 1737.43) (3088.35 4057.87))" "[PinPair] <uTiL>cId3537<uTiL>.AT3:<uTiL>cId4703<uTiL>.6 ((2875.18 1737.43) (3088.35 4006.69))" list(3088.350000 4006.690000) nil)@@@list("amy_chou" "2015/01/12 09:58:34" nil "P143000034-PC" "5s-ippbt-sk.x01")@@@list("jennifer_hsu" "2015/01/12 14:37:19" nil "p143000039-pc" "5s-ippbt-sk.x01") | list("[Electrical] ALL" "123.Diffpair Max Uncoupled Length" "200 MIL [DIFFP_UNCOUPLED_LENGTH]" "207.9 MIL" "-7.90 MIL" "DRC ERROR CLASS/ALL" "[PinPair] <uTiL>cId3537<uTiL>.AP3:<uTiL>cId4703<uTiL>.10 ((2875.18 1775.69) (3088.35 3904.33))" "[PinPair] <uTiL>cId3537<uTiL>.AP2:<uTiL>cId4703<uTiL>.12 ((2902.7 1775.69) (3088.35 3853.15))" list(3088.350000 3853.150000) nil)@@@list("amy_chou" "2015/01/12 09:58:36" nil "P143000034-PC" "5s-ippbt-sk.x01")@@@list("jennifer_hsu" "2015/01/12 14:37:20" nil "p143000039-pc" "5s-ippbt-sk.x01") | list("[Package] TOP" "148.Pkg to Place Keepout Spacing" "0 MIL [NONE]" "257.09 MIL" "-257.09 MIL" "DRC ERROR CLASS/PACKAGE_TOP" "[Shape] Package Keepout/Top ((2919.55 -318.35) (3300.93 119.6))" "[Shape] Package Geometry/Place_Bound_Top ((2999.55 -238.35) (3220.93 39.6))" list(3220.930000 -155.630000) nil)@@@list("amy_chou" "2015/01/12 09:59:01" nil "P143000034-PC" "5s-ippbt-sk.x01")@@@list("jennifer_hsu" "2015/01/12 14:37:30" nil "p143000039-pc" "5s-ippbt-sk.x01") | list("[Package] BOTTOM" "192.Pkg to Pkg Spacing" "0 MIL [PACKAGE_HEIGHT_MIN]" "2 MIL" "-2.00 MIL" "DRC ERROR CLASS/PACKAGE_BOTTOM" "[Shape] Package Geometry/Place_Bound_Bottom ((3263.07 2797.9) (3546.93 3172.1))" "[Shape] Package Geometry/Place_Bound_Bottom ((3377.19 2883.19) (3432.81 2976.81))" list(3377.190000 2883.190000) nil)@@@list("amy_chou" "2015/01/12 09:59:26" nil "P143000034-PC" "5s-ippbt-sk.x01")@@@list("jennifer_hsu" "2015/01/12 14:37:45" nil "p143000039-pc" "5s-ippbt-sk.x01") | list("[Package] BOTTOM" "193.Pkg to Pkg Spacing" "0 MIL [PACKAGE_HEIGHT_MIN]" "2 MIL" "-2.00 MIL" "DRC ERROR CLASS/PACKAGE_BOTTOM" "[Shape] Package Geometry/Place_Bound_Bottom ((3308.07 597.9) (3591.93 972.1))" "[Shape] Package Geometry/Place_Bound_Bottom ((3422.19 793.19) (3477.81 886.81))" list(3422.190000 793.190000) nil)@@@list("amy_chou" "2015/01/12 09:59:27" nil "P143000034-PC" "5s-ippbt-sk.x01")@@@list("jennifer_hsu" "2015/01/12 14:37:45" nil "p143000039-pc" "5s-ippbt-sk.x01") | list("[Package] BOTTOM" "194.Pkg to Pkg Spacing" "0 MIL [PACKAGE_HEIGHT_MIN]" "2 MIL" "-2.00 MIL" "DRC ERROR CLASS/PACKAGE_BOTTOM" "[Shape] Package Geometry/Place_Bound_Bottom ((3308.07 597.9) (3591.93 972.1))" "[Shape] Package Geometry/Place_Bound_Bottom ((3422.19 683.19) (3477.81 776.81))" list(3422.190000 683.190000) nil)@@@list("amy_chou" "2015/01/12 09:59:28" nil "P143000034-PC" "5s-ippbt-sk.x01")@@@list("jennifer_hsu" "2015/01/12 14:37:46" nil "p143000039-pc" "5s-ippbt-sk.x01") | list("[Package] BOTTOM" "191.Pkg to Pkg Spacing" "0 MIL [PACKAGE_HEIGHT_MIN]" "2 MIL" "-2.00 MIL" "DRC ERROR CLASS/PACKAGE_BOTTOM" "[Shape] Package Geometry/Place_Bound_Bottom ((3263.07 2797.9) (3546.93 3172.1))" "[Shape] Package Geometry/Place_Bound_Bottom ((3377.19 2993.19) (3432.81 3086.81))" list(3432.810000 2993.190000) nil)@@@list("amy_chou" "2015/01/12 09:59:26" nil "P143000034-PC" "5s-ippbt-sk.x01")@@@list("jennifer_hsu" "2015/01/12 14:37:45" nil "p143000039-pc" "5s-ippbt-sk.x01") | list("[Package] TOP" "168.Pkg to Place Keepin Spacing" "0 MIL [NONE]" "0 MIL" "0.00 MIL" "DRC ERROR CLASS/PACKAGE_TOP" "[Shape] Package Keepin/All ((-353.71 -312.37) (4448.18 4461.96))" "[Shape] Package Geometry/Place_Bound_Top ((3509.31 -277.48) (3730.69 0.47))" list(3509.310000 -194.260000) nil)@@@list("amy_chou" "2015/01/12 09:59:13" nil "P143000034-PC" "5s-ippbt-sk.x01")@@@list("jennifer_hsu" "2015/01/12 14:37:37" nil "p143000039-pc" "5s-ippbt-sk.x01") | list("[Package] TOP" "174.Pkg to Pkg Spacing" "0 MIL [PACKAGE_HEIGHT_MIN]" "2 MIL" "-2.00 MIL" "DRC ERROR CLASS/PACKAGE_TOP" "[Shape] Package Geometry/Place_Bound_Top ((3703.99 3654.12) (3876.01 3795.88))" "[Shape] Package Geometry/Place_Bound_Top ((3663.19 3737.19) (3756.81 3792.81))" list(3703.990000 3792.810000) nil)@@@list("amy_chou" "2015/01/12 09:59:15" nil "P143000034-PC" "5s-ippbt-sk.x01")@@@list("jennifer_hsu" "2015/01/12 14:37:39" nil "p143000039-pc" "5s-ippbt-sk.x01") | list("[Package] TOP" "175.Pkg to Pkg Spacing" "0 MIL [PACKAGE_HEIGHT_MIN]" "2 MIL" "-2.00 MIL" "DRC ERROR CLASS/PACKAGE_TOP" "[Shape] Package Geometry/Place_Bound_Top ((3703.99 3654.12) (3876.01 3795.88))" "[Shape] Package Geometry/Place_Bound_Top ((3663.19 3657.19) (3756.81 3712.81))" list(3703.990000 3712.810000) nil)@@@list("amy_chou" "2015/01/12 09:59:16" nil "P143000034-PC" "5s-ippbt-sk.x01")@@@list("jennifer_hsu" "2015/01/12 14:37:39" nil "p143000039-pc" "5s-ippbt-sk.x01") | list("[Package] TOP" "169.Pkg to Place Keepout Spacing" "0 MIL [NONE]" "257.09 MIL" "-257.09 MIL" "DRC ERROR CLASS/PACKAGE_TOP" "[Shape] Package Geometry/Place_Bound_Top ((3509.31 -277.48) (3730.69 0.47))" "[Shape] Package Keepout/Top ((3429.31 -357.48) (3810.69 80.47))" list(3730.690000 -194.760000) nil)@@@list("amy_chou" "2015/01/12 09:59:12" nil "P143000034-PC" "5s-ippbt-sk.x01")@@@list("jennifer_hsu" "2015/01/12 14:37:37" nil "p143000039-pc" "5s-ippbt-sk.x01") | list("[Package] TOP" "166.Pkg to Place Keepout Spacing" "0 MIL [NONE]" "263.78 MIL" "-263.78 MIL" "DRC ERROR CLASS/PACKAGE_TOP" "[Shape] Package Keepout/Top ((3336.22 3966.6) (3891.32 4653.03))" "[Shape] Package Geometry/Place_Bound_Top ((3416.22 4046.61) (3811.32 4573.03))" list(3801.860000 4265.400000) nil)@@@list("amy_chou" "2015/01/12 09:59:11" nil "P143000034-PC" "5s-ippbt-sk.x01")@@@list("jennifer_hsu" "2015/01/12 14:37:36" nil "p143000039-pc" "5s-ippbt-sk.x01") | list("[Package] TOP" "167.Pkg to Place Keepin Spacing" "0 MIL [NONE]" "0 MIL" "0.00 MIL" "DRC ERROR CLASS/PACKAGE_TOP" "[Shape] Package Keepin/All ((-353.71 -312.37) (4448.18 4461.96))" "[Shape] Package Geometry/Place_Bound_Top ((3416.22 4046.61) (3811.32 4573.03))" list(3811.320000 4430.470000) nil)@@@list("amy_chou" "2015/01/12 09:59:12" nil "P143000034-PC" "5s-ippbt-sk.x01")@@@list("jennifer_hsu" "2015/01/12 14:37:36" nil "p143000039-pc" "5s-ippbt-sk.x01") | list("[Electrical] ALL" "129.Diffpair Max Uncoupled Length" "200 MIL [DIFFP_UNCOUPLED_LENGTH]" "204.6 MIL" "-4.60 MIL" "DRC ERROR CLASS/ALL" "[PinPair] <uTiL>cId3653<uTiL>.9:<uTiL>cId3537<uTiL>.K6 ((3966.85 1516.61) (2825.31 2235.92))" "[PinPair] <uTiL>cId3653<uTiL>.8:<uTiL>cId3537<uTiL>.K7 ((3966.85 1595.35) (2797.31 2235.92))" list(3966.850000 1595.350000) nil)@@@list("amy_chou" "2015/01/12 09:58:41" nil "P143000034-PC" "5s-ippbt-sk.x01")@@@list("jennifer_hsu" "2015/01/12 14:37:23" nil "p143000039-pc" "5s-ippbt-sk.x01") | list("[Package] TOP" "141.Pkg to Place Keepout Spacing" "0 MIL [NONE]" "240.55 MIL" "-240.55 MIL" "DRC ERROR CLASS/PACKAGE_TOP" "[Shape] Package Keepout/Top ((3842.56 1294.61) (4609.26 2053.57))" "[Shape] Package Geometry/Place_Bound_Top ((3922.56 1374.61) (4529.26 1973.57))" list(3970.710000 1386.370000) nil)@@@list("amy_chou" "2015/01/12 09:58:57" nil "P143000034-PC" "5s-ippbt-sk.x01")@@@list("jennifer_hsu" "2015/01/12 14:37:27" nil "p143000039-pc" "5s-ippbt-sk.x01") | list("[Package] TOP" "143.Pkg to Place Keepout Spacing" "0 MIL [NONE]" "236.61 MIL" "-236.61 MIL" "DRC ERROR CLASS/PACKAGE_TOP" "[Shape] Package Keepout/Top ((3878.01 2119.73) (4609.27 2878.69))" "[Shape] Package Geometry/Place_Bound_Top ((3958.01 2199.73) (4529.27 2798.69))" list(3973.390000 2213.640000) nil)@@@list("amy_chou" "2015/01/12 09:58:58" nil "P143000034-PC" "5s-ippbt-sk.x01")@@@list("jennifer_hsu" "2015/01/12 14:37:28" nil "p143000039-pc" "5s-ippbt-sk.x01") | list("[Package] BOTTOM" "182.Pkg to Place Keepin Spacing" "0 MIL [NONE]" "0 MIL" "0.00 MIL" "DRC ERROR CLASS/PACKAGE_BOTTOM" "[Shape] Package Keepin/All ((-353.71 -312.37) (4448.18 4461.96))" "[Shape] Package Geometry/Place_Bound_Bottom ((3896.67 -217.5) (4331.67 217.5))" list(4065.830000 -212.060000) nil)@@@list("amy_chou" "2015/01/12 09:59:19" nil "P143000034-PC" "5s-ippbt-sk.x01")@@@list("jennifer_hsu" "2015/01/12 14:37:41" nil "p143000039-pc" "5s-ippbt-sk.x01") | list("[Package] TOP" "144.Pkg to Place Keepin Spacing" "0 MIL [NONE]" "0 MIL" "0.00 MIL" "DRC ERROR CLASS/PACKAGE_TOP" "[Shape] Package Keepin/All ((-353.71 -312.37) (4448.18 4461.96))" "[Shape] Package Geometry/Place_Bound_Top ((3958.01 2199.73) (4529.27 2798.69))" list(4448.180000 2229.330000) nil)@@@list("amy_chou" "2015/01/12 09:58:59" nil "P143000034-PC" "5s-ippbt-sk.x01")@@@list("jennifer_hsu" "2015/01/12 14:37:28" nil "p143000039-pc" "5s-ippbt-sk.x01") | list("[Package] TOP" "142.Pkg to Place Keepin Spacing" "0 MIL [NONE]" "0 MIL" "0.00 MIL" "DRC ERROR CLASS/PACKAGE_TOP" "[Shape] Package Keepin/All ((-353.71 -312.37) (4448.18 4461.96))" "[Shape] Package Geometry/Place_Bound_Top ((3922.56 1374.61) (4529.26 1973.57))" list(4448.180000 1406.180000) nil)@@@list("amy_chou" "2015/01/12 09:58:57" nil "P143000034-PC" "5s-ippbt-sk.x01")@@@list("jennifer_hsu" "2015/01/12 14:37:27" nil "p143000039-pc" "5s-ippbt-sk.x01") | list("[Package] TOP" "161.Pkg to Place Keepin Spacing" "0 MIL [NONE]" "0 MIL" "0.00 MIL" "DRC ERROR CLASS/PACKAGE_TOP" "[Shape] Package Keepin/All ((-353.71 -312.37) (4448.18 4461.96))" "[Shape] Package Geometry/Place_Bound_Top ((4066.69 323.23) (4448.95 1209.45))" list(4448.180000 323.230000) nil)@@@list("amy_chou" "2015/01/12 09:59:09" nil "P143000034-PC" "5s-ippbt-sk.x01")@@@list("jennifer_hsu" "2015/01/12 14:37:34" nil "p143000039-pc" "5s-ippbt-sk.x01") | list("[Package] TOP" "160.Pkg to Place Keepout Spacing" "0 MIL [NONE]" "165.35 MIL" "-165.35 MIL" "DRC ERROR CLASS/PACKAGE_TOP" "[Shape] Package Geometry/Place_Bound_Top ((4066.69 323.23) (4448.95 1209.45))" "[Shape] Package Keepout/Top ((4046.69 303.23) (4468.95 1229.45))" list(4448.950000 323.230000) nil)@@@list("amy_chou" "2015/01/12 09:59:08" nil "P143000034-PC" "5s-ippbt-sk.x01")@@@list("jennifer_hsu" "2015/01/12 14:37:34" nil "p143000039-pc" "5s-ippbt-sk.x01")
